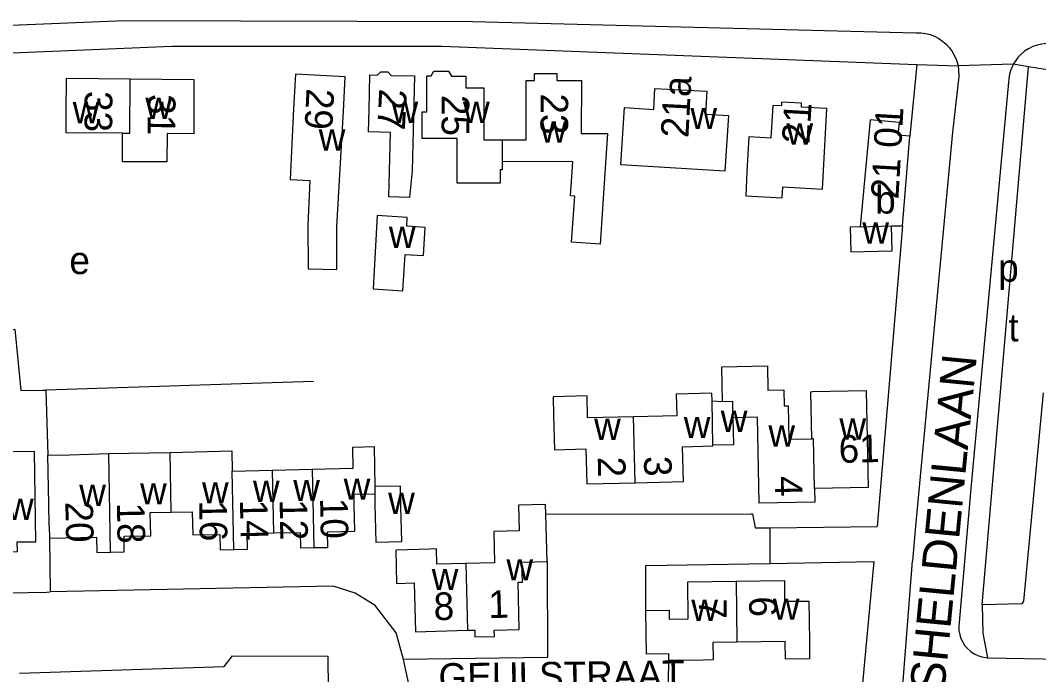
# Model space of a CAD drawing. Extents: x 156721 to 158827, y 386657 to 388950.
# Drawn here: x 158105.4 to 158252.9, y 387725.3 to 387820.1 of the extents above; entities that cross this region are included whole.
import ezdxf

# ---------------------------------------------------------------- set-up
doc = ezdxf.new("R2010")
doc.units = 0
for name, color, linetype in [('BLT_Basislijn', 7, 'Continuous'), ('BLT_Bebouwing', 7, 'Continuous'), ('BLT_Centroide', 7, 'Continuous'), ('BLT_Huisnummer', 7, 'Continuous'), ('BLT_Huisnummer_ tussenligend', 7, 'Continuous'), ('BLT_Onderverdeling_panden', 7, 'Continuous'), ('BLT_Straatnaam', 7, 'Continuous'), ('BLT_Straatnaam_verkleind', 7, 'Continuous'), ('BLT_Vlakafsluiter', 7, 'Continuous')]:
    doc.layers.add(name, color=color, linetype=linetype)

msp = doc.modelspace()

# ---------------------------------------------------------------- linework, layer by layer
at = {"layer": 'BLT_Basislijn'}
for p, q in [((158235.29, 387813.71), (158234.26, 387803.32)), ((158235.29, 387813.71), (158241.26, 387813.48)), ((158251.46, 387813.36), (158249.26, 387813.72)), ((158244.75, 387735.41), (158251.46, 387813.36)), ((158258, 387812.32), (158251.46, 387813.36)), ((158248.56, 387811.14), (158243.17, 387752.79)), ((158233.21, 387790.33), (158229.52, 387746.73)), ((158147.86, 387767.77), (158109.06, 387766.52)), ((158109.06, 387766.52), (158109.35, 387757.07)), ((158243.17, 387752.79), (158241.41, 387732.83)), ((158214, 387746.56), (158229.52, 387746.73)), ((158214, 387746.56), (158214, 387741.38)), ((158235.07, 387746.79), (158234.67, 387741.75)), ((158109.58, 387745.05), (158109.69, 387737.25)), ((158214, 387741.38), (158229.04, 387741.65)), ((158229.04, 387741.65), (158224.79, 387696.34)), ((158134.91, 387726.43), (158136.1, 387728)), ((158136.1, 387728), (158149.92, 387727.95)), ((158149.92, 387727.95), (158149.97, 387723.07)), ((158105.26, 387725.49), (158134.91, 387726.43)), ((158245.52, 387727.73), (158327.44, 387726.03))]:
    msp.add_line(p, q, dxfattribs=at)
for points in [[(158050, 387817.19), (158120.45, 387820.09), (158170.93, 387819.93), (158235.15, 387818.28)], [(158235.15, 387818.28), (158235.84, 387818.27), (158236.52, 387818.19), (158237.19, 387818.02), (158237.84, 387817.78), (158238.45, 387817.46), (158239.02, 387817.08), (158239.55, 387816.63), (158240.02, 387816.12), (158240.42, 387815.57), (158240.76, 387814.97), (158241.03, 387814.33), (158241.23, 387813.67), (158241.26, 387813.48)], [(158050, 387813.1), (158127.35, 387816.35), (158166.43, 387816.35), (158235.29, 387813.71)], [(158255.41, 387816.62), (158254.74, 387816.71), (158254.06, 387816.72), (158253.38, 387816.65), (158252.72, 387816.51), (158252.08, 387816.28), (158251.47, 387815.98), (158250.9, 387815.61), (158250.38, 387815.18), (158249.91, 387814.69), (158249.51, 387814.15), (158249.26, 387813.72)], [(158241.26, 387813.48), (158241.34, 387812.99), (158241.39, 387811.96)], [(158249.26, 387813.72), (158249.17, 387813.56), (158248.9, 387812.94), (158248.71, 387812.29), (158248.59, 387811.62), (158248.56, 387811.14)], [(158241.39, 387811.96), (158240.43, 387803.89), (158235.07, 387746.79)], [(158050, 387774.05), (158104.59, 387775.34), (158105.44, 387766.45), (158108.59, 387766.5), (158109.06, 387766.52)], [(158253.61, 387766.09), (158250.74, 387735.91), (158250.5, 387735.52), (158244.75, 387735.41)], [(158181.52, 387748.52), (158211.24, 387748.59), (158211.46, 387748.56), (158211.84, 387746.54), (158214, 387746.56)], [(158181.72, 387741.68), (158181.78, 387727.76), (158160.89, 387727.45)], [(158196.02, 387734.57), (158195.99, 387741.07), (158214, 387741.38)], [(158230.7, 387698.25), (158233.04, 387721.24), (158234.67, 387741.75)], [(158096.94, 387738.43), (158099.08, 387738.44), (158101.06, 387737.07), (158109.15, 387737.24), (158109.69, 387737.25)], [(158160.89, 387727.45), (158159.82, 387731.32), (158156.79, 387735.31), (158153.9, 387737.09), (158150.72, 387738.11), (158109.69, 387737.25)], [(158244.75, 387735.41), (158244.84, 387731.29), (158245.52, 387727.73)], [(158241.41, 387732.83), (158241.36, 387732.24), (158241.38, 387731.65), (158241.49, 387731.06), (158241.68, 387730.49), (158241.93, 387729.96), (158242.26, 387729.46), (158242.65, 387729.02), (158243.1, 387728.62), (158243.6, 387728.3), (158244.14, 387728.04), (158244.7, 387727.85), (158245.29, 387727.75), (158245.52, 387727.73)], [(158162.37, 387721.93), (158161.92, 387722.8), (158160.89, 387727.45)], [(158183.78, 387722.13), (158190.28, 387721.98), (158190.27, 387718.43), (158199.18, 387718.42), (158199.34, 387727.31)]]:
    msp.add_lwpolyline(points, dxfattribs=at)
at = {"layer": 'BLT_Bebouwing'}
for p, q in [((158233.21, 387790.33), (158234.26, 387803.32)), ((158231.61, 387790.29), (158233.21, 387790.33)), ((158207.13, 387764.83), (158205.6, 387764.9)), ((158136.08, 387754.78), (158141.91, 387754.92)), ((158141.91, 387754.92), (158147.71, 387755.07)), ((158181.72, 387741.68), (158181.52, 387748.52)), ((158109.55, 387746.79), (158109.58, 387745.05))]:
    msp.add_line(p, q, dxfattribs=at)
for points in [[(158152.2, 387806.92), (158152.45, 387811.92), (158145.23, 387812.28), (158144.98, 387807.28), (158144.78, 387803.2), (158144.47, 387797.02), (158147.34, 387796.88), (158147.02, 387790.42), (158147.08, 387784.08), (158151.22, 387784), (158151.22, 387790.22), (158152.2, 387806.92)], [(158162.14, 387798.26), (158161.77, 387794.43), (158158.78, 387794.51), (158159.03, 387803.83), (158155.82, 387803.92), (158155.91, 387807.18), (158156.04, 387812.18), (158157.1, 387812.15), (158157.62, 387812.64), (158158.65, 387812.61), (158159.13, 387812.1), (158162.5, 387812.04), (158162.14, 387798.26)], [(158175.17, 387799.62), (158175.17, 387798.45), (158174.9, 387798.45), (158174.9, 387796.48), (158168.69, 387796.48), (158168.68, 387802.95), (158164.34, 387802.95), (158163.62, 387802.96), (158163.62, 387806.84), (158164.27, 387806.84), (158164.27, 387812.05), (158164.89, 387812.05), (158165.29, 387812.74), (158167.43, 387812.74), (158167.86, 387811.99), (158169.92, 387811.99), (158169.92, 387810.3), (158172.56, 387810.3), (158172.55, 387802.79), (158175.17, 387802.78)], [(158175.17, 387802.78), (158178.65, 387802.78), (158178.65, 387811.37), (158179.87, 387811.37), (158179.87, 387812.37), (158183.12, 387812.37), (158183.12, 387811.37), (158186.67, 387811.37), (158186.66, 387803.68), (158190.46, 387803.68), (158190.12, 387798.69)], [(158120.19, 387803.75), (158112.03, 387803.77), (158112.03, 387806.69), (158112.04, 387811.69), (158121.28, 387811.61)], [(158121.28, 387811.61), (158130.52, 387811.53), (158130.51, 387806.53), (158130.51, 387803.66), (158126.63, 387803.67), (158126.62, 387799.59), (158120.18, 387799.6), (158120.19, 387803.75)], [(158218.34, 387795.82), (158221.61, 387795.64), (158222.26, 387807.3), (158218.56, 387807.51), (158218.59, 387808.08), (158215.69, 387808.24), (158215.66, 387807.69), (158214.41, 387807.76), (158214.14, 387803.01), (158210.94, 387803.19), (158210.66, 387798.2), (158210.51, 387794.66), (158215.76, 387794.36), (158215.85, 387795.96), (158218.34, 387795.82)], [(158234.26, 387803.32), (158232.59, 387803.47), (158232.75, 387805.28), (158228.51, 387805.66), (158227.07, 387790.18)], [(158190.12, 387798.69), (158189.39, 387787.67), (158185.25, 387787.95), (158185.7, 387794.63), (158185.1, 387794.67), (158185.43, 387799.61), (158175.17, 387799.62)], [(158227.07, 387790.18), (158225.62, 387790.14), (158225.71, 387786.54), (158231.71, 387786.69), (158231.61, 387790.29)], [(158207.13, 387764.83), (158207.04, 387769.89), (158213.64, 387770), (158213.7, 387766.5), (158216, 387766.54), (158216.04, 387764.24), (158216.63, 387764.25), (158216.73, 387759.38), (158220.05, 387759.45)], [(158220.05, 387759.45), (158219.91, 387766.27), (158220.16, 387766.28), (158227.94, 387766.43), (158228.22, 387752.4), (158220.45, 387752.24)], [(158194.23, 387762.62), (158187.58, 387762.47), (158187.5, 387765.66), (158182.58, 387765.54), (158182.64, 387762.87), (158182.76, 387757.87), (158187.32, 387757.98), (158187.44, 387752.91), (158194.45, 387753.08)], [(158205.6, 387764.9), (158205.57, 387766.04), (158200.43, 387765.92), (158200.51, 387762.77), (158194.23, 387762.62)], [(158205.71, 387758.56), (158208.74, 387758.63), (158208.65, 387762.49)], [(158220.45, 387752.24), (158220.49, 387750.28), (158212.45, 387750.12), (158212.35, 387755.12), (158212.19, 387762.56), (158208.65, 387762.49)], [(158107.63, 387744.54), (158107.41, 387757.62), (158102.74, 387757.54), (158102.11, 387752.28), (158098.96, 387752.22)], [(158118.18, 387757.31), (158127.1, 387757.48)], [(158127.1, 387757.48), (158136.01, 387757.69), (158136.08, 387754.78)], [(158147.71, 387755.07), (158153.62, 387755.21), (158153.55, 387758.26), (158156.63, 387758.33), (158156.75, 387752.53)], [(158194.45, 387753.08), (158201.46, 387753.24), (158201.34, 387758.3), (158205.71, 387758.41), (158205.71, 387758.56)], [(158109.35, 387757.07), (158112.51, 387757.13), (158118.18, 387757.31)], [(158109.55, 387746.79), (158109.49, 387750), (158109.35, 387757.07)], [(158147.93, 387743.68), (158149.91, 387743.72), (158149.86, 387745.98), (158153.85, 387746.06), (158153.76, 387750), (158153.73, 387751.42), (158156.72, 387751.49)], [(158156.72, 387751.49), (158156.75, 387750), (158156.87, 387744.49), (158160.64, 387744.57), (158160.53, 387749.57), (158160.52, 387750), (158160.47, 387752.6), (158156.75, 387752.53)], [(158118.46, 387743.03), (158120.44, 387743.07), (158120.4, 387745.32), (158124.28, 387745.4), (158124.21, 387748.75), (158127.25, 387748.8)], [(158127.25, 387748.8), (158130.29, 387748.86), (158130.35, 387745.51), (158134.26, 387745.58), (158134.31, 387743.37), (158136.3, 387743.41)], [(158181.52, 387748.52), (158181.49, 387749.93), (158177.55, 387749.82), (158177.66, 387746.11), (158173.97, 387746.01), (158174.1, 387741.49), (158169.92, 387741.37)], [(158136.3, 387743.41), (158138.3, 387743.45), (158138.26, 387745.72), (158142.09, 387745.8)], [(158142.09, 387745.8), (158145.92, 387745.87), (158145.96, 387743.64), (158147.93, 387743.68)], [(158099.15, 387740.79), (158101.11, 387740.82), (158101.07, 387743.04), (158104.95, 387743.1), (158104.92, 387744.5), (158107.63, 387744.54)], [(158109.58, 387745.05), (158116.43, 387745.19), (158116.47, 387742.99), (158118.46, 387743.03)], [(158169.92, 387741.37), (158165.73, 387741.26), (158165.67, 387743.49), (158164.77, 387743.46), (158159.77, 387743.32), (158159.9, 387738.49), (158162.45, 387738.56), (158162.65, 387731.49), (158170.18, 387731.7)], [(158170.18, 387731.7), (158171.22, 387731.73), (158171.25, 387730.74), (158174.07, 387730.82), (158174.05, 387731.73), (158177.68, 387731.83), (158177.49, 387738.65), (158178.14, 387738.67), (158178.06, 387741.58), (158181.72, 387741.68)], [(158196.02, 387734.57), (158199.39, 387734.61), (158199.41, 387733.32), (158202.17, 387733.36), (158202.1, 387738.71), (158209.09, 387738.8)], [(158209.09, 387738.8), (158216.09, 387738.89), (158216.12, 387735.9), (158219.63, 387735.94), (158219.71, 387730.12), (158219.74, 387727.58), (158216.24, 387727.53), (158216.2, 387730.07), (158209.21, 387729.98)], [(158199.34, 387727.31), (158199.33, 387728.28), (158196.1, 387728.24), (158196.02, 387734.57)], [(158209.21, 387729.98), (158205.72, 387729.93), (158205.76, 387727.4), (158204.34, 387727.38), (158199.34, 387727.31)]]:
    msp.add_lwpolyline(points, dxfattribs=at)
for points in [[(158192.37, 387799.16), (158192.9, 387807.46), (158197.16, 387807.19), (158197.31, 387810.21), (158204.85, 387809.82), (158204.68, 387806.48), (158207.98, 387806.31), (158207.46, 387798.21)], [(158157.1, 387791.79), (158156.48, 387781.16), (158160.82, 387780.91), (158161.12, 387786.16), (158163.78, 387786.01), (158164.02, 387790.09), (158161.36, 387790.24), (158161.44, 387791.54)]]:
    msp.add_lwpolyline(points, close=True, dxfattribs=at)
at = {"layer": 'BLT_Onderverdeling_panden'}
for p, q in [((158175.17, 387802.78), (158175.17, 387799.62)), ((158227.07, 387790.18), (158231.61, 387790.29)), ((158205.71, 387758.56), (158205.6, 387764.9)), ((158194.45, 387753.08), (158194.23, 387762.62)), ((158127.25, 387748.8), (158127.1, 387757.48)), ((158118.46, 387743.03), (158118.18, 387757.31)), ((158136.3, 387743.41), (158136.08, 387754.78)), ((158142.09, 387745.8), (158141.91, 387754.92)), ((158147.93, 387743.68), (158147.71, 387755.07)), ((158156.75, 387752.53), (158156.72, 387751.49)), ((158169.92, 387741.37), (158170.18, 387731.7)), ((158209.09, 387738.8), (158209.21, 387729.98))]:
    msp.add_line(p, q, dxfattribs=at)
for points in [[(158120.19, 387803.75), (158121.22, 387803.75), (158121.28, 387811.61)], [(158208.65, 387762.49), (158208.62, 387763.63), (158208.6, 387764.87), (158207.13, 387764.83)], [(158220.45, 387752.24), (158220.3, 387759.45), (158220.05, 387759.45)]]:
    msp.add_lwpolyline(points, dxfattribs=at)
at = {"layer": 'BLT_Vlakafsluiter'}
msp.add_line((158249.26, 387813.72), (158241.26, 387813.48), dxfattribs=at)

# ---------------------------------------------------------------- texts
at = {"layer": 'BLT_Centroide'}
for s, p in [('w', (158112.97, 387805.17)), ('w', (158123.49, 387805.79)), ('w', (158159.16, 387805.22)), ('w', (158169.52, 387805.22)), ('w', (158202.47, 387804.34)), ('w', (158180.7, 387802.36)), ('w', (158216.39, 387802.08)), ('w', (158148.61, 387801.22)), ('b', (158229.25, 387792.09)), ('w', (158158.78, 387787.11)), ('w', (158227.39, 387787.75)), ('e', (158112.48, 387783.32)), ('p', (158247.07, 387782.22)), ('t', (158248.55, 387773.56)), ('w', (158206.87, 387760.43)), ('w', (158188.52, 387759.28)), ('w', (158201.51, 387759.56)), ('w', (158224.06, 387759.33)), ('w', (158213.77, 387758.33)), ('w', (158122.73, 387749.94)), ('w', (158131.7, 387750.09)), ('w', (158139.08, 387750.3)), ('w', (158144.92, 387750.42)), ('w', (158152.23, 387750.61)), ('w', (158113.91, 387749.72)), ('w', (158158.67, 387748.55)), ('w', (158103.45, 387747.69)), ('w', (158175.81, 387738.92)), ('w', (158164.98, 387737.52)), ('w', (158202.6, 387733.06)), ('w', (158214.42, 387733.22))]:
    msp.add_text(s, height=4, dxfattribs=at).set_placement(p)
at = {"layer": 'BLT_Huisnummer'}
for s, rotation, p in [('21a', 87.044, (158202.17, 387802.99)), ('33', 269.4973, (158114.72, 387809.87)), ('31', 269.4973, (158123.87, 387809.42)), ('29', 267.1502, (158146.86, 387810.29)), ('27', 267.1456, (158157.39, 387810.24)), ('25', 269.967, (158166.42, 387809.29)), ('23', 269.9805, (158180.75, 387809.5)), ('21', 86.8075, (158219.71, 387802.14)), ('21 01', 86.8145, (158232.61, 387794.1)), ('61', 1.1718, (158223.99, 387755.96)), ('2', 271.3343, (158189.04, 387756.81)), ('3', 271.3202, (158195.73, 387756.92)), ('4', 271.1689, (158214.67, 387754.02)), ('20', 271.1319, (158111.89, 387750.32)), ('14', 271.1319, (158137.19, 387750.61)), ('10', 271.1319, (158148.8, 387750.86)), ('8', 1.5958, (158165.31, 387733.15)), ('1', 1.5911, (158173.23, 387733.45)), ('7', 270.7517, (158203.71, 387736.27)), ('6', 270.7603, (158210.97, 387736.59))]:
    msp.add_text(s, height=4, rotation=rotation, dxfattribs=at).set_placement(p)
at = {"layer": 'BLT_Huisnummer_ tussenligend'}
for s, p in [('16', (158131.28, 387750.5)), ('12', (158142.94, 387750.64)), ('18', (158119.36, 387750.18))]:
    msp.add_text(s, height=4, rotation=271.1319, dxfattribs=at).set_placement(p)
at = {"layer": 'BLT_Straatnaam'}
msp.add_text('VERZETSHELDENLAAN', height=5, rotation=84.4521, dxfattribs=at).set_placement((158236.69, 387696.35))
at = {"layer": 'BLT_Straatnaam_verkleind'}
msp.add_text('GEULSTRAAT', height=4, rotation=0.7158, dxfattribs=at).set_placement((158165.99, 387722.91))

doc.saveas('drawing.dxf')
